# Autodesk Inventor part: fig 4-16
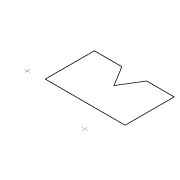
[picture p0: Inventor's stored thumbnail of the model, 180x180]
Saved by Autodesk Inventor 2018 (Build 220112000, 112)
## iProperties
Created: 2005-02
Part Number: fig 4-16
Document SubType Name: Modeling
Designer: CADCIM
Manufacturer: Standard
Standards Organization: Custom
Density: 1 g/cm^3
Material: Generic
Appearance: Default
Author: CADCIM
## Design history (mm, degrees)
sketch "Sketch1"
  geometry: L1 (-25.19, 27.524)-(-25.19, 5.557); L2 (-25.19, 5.557)-(10.567, 5.557); L3 (10.567, 5.557)-(10.567, 27.524); L4 (10.567, 27.524)-(-1.76, 27.524); L5 (-1.76, 27.524)-(-7.312, 18.449); L6 (-7.312, 18.449)-(-12.863, 27.524); L7 (-12.863, 27.524)-(-25.19, 27.524); 2 further points
  constraints: 14 end point, 3 equal length, 3 parallel, 1 perpendicular, 1 vertical, 1 other
